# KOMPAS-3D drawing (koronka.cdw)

Views: Вид 1
Referenced files: Чертеж1.cdw
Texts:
  Коронка
  Текст на чертеже
  Размерные надписи
  Шероховатость
  Линия-выноска #1
  Линия-выноска #2
  Линия-выноска #3
  Отклонения формы и база
  Заголовок таблицы
  Ячейка таблицы
  Стрелка вида
  Обозначение изменения
  Фигурная скобка
  Номер узла
  Марка координационной оси
  VRCB
  Выносная надпись
  Обозначение узла
  Марка/позиционное обозначение с линией-выноской
  Марка/позиционное обозначение на линии
  Марка/позиционное обозначение без линии-выноски
  Symbol type A
  R 0.5max
  Чугун СЧ15 ГОСТ1412-85
Dimensions and other numbers on the sheet: 61 00 Т 03; 7; 36; 17; 12; 4; 2; 3.2; 6.3; 10; 1:1; 1; 8; 61 00 Т 03-; 0; 3; 5; 6; 9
